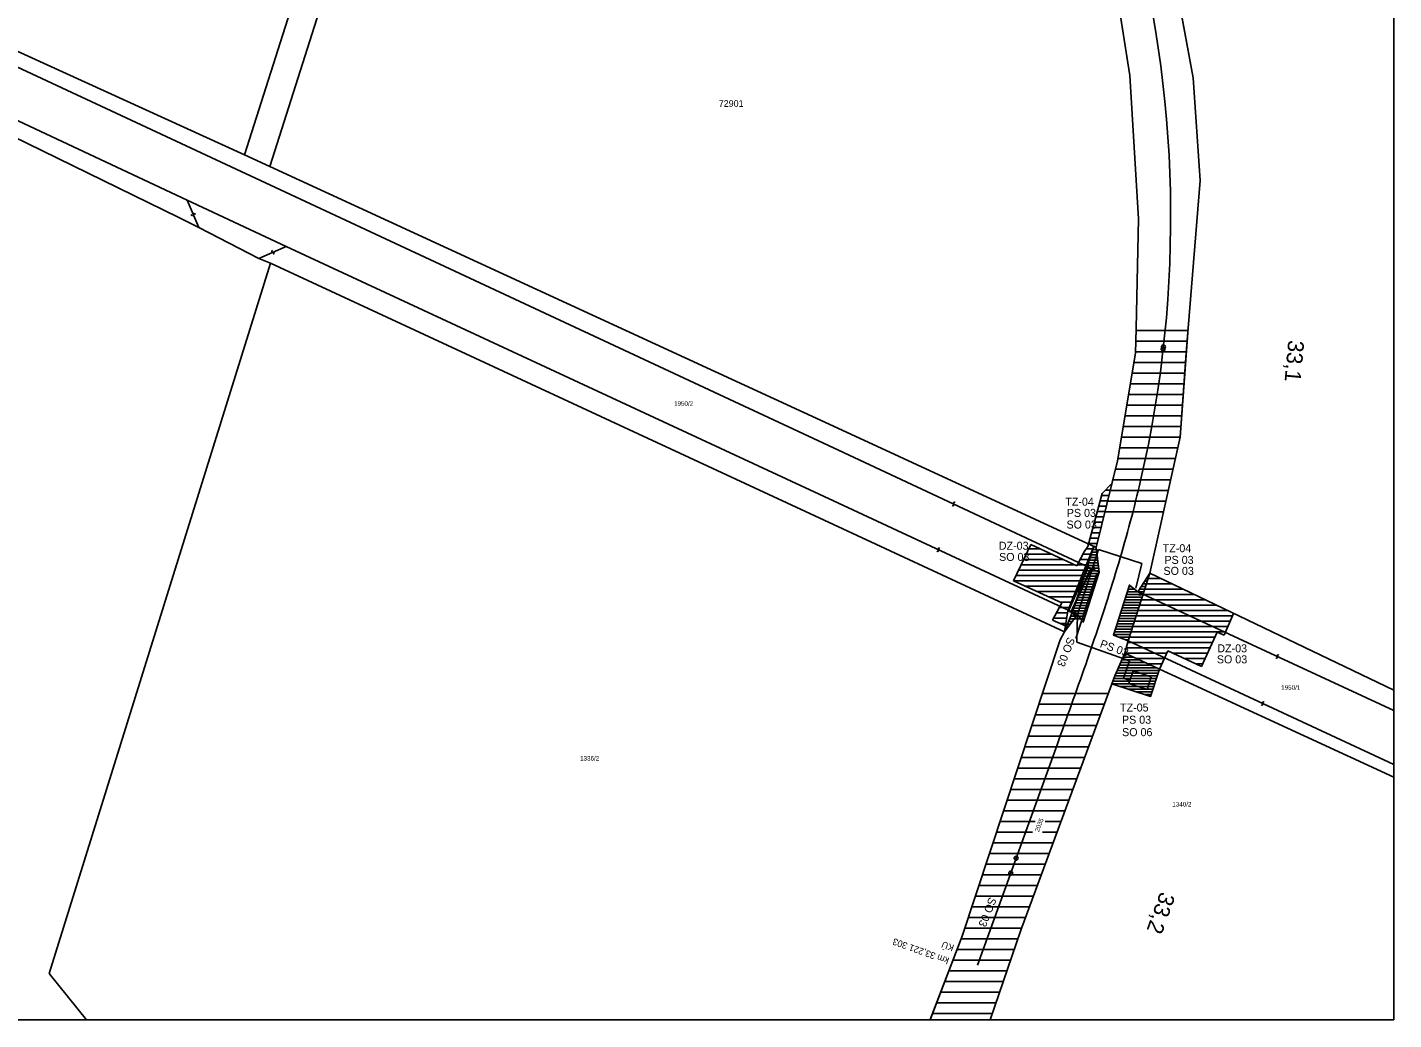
# Model space of a CAD drawing. Extents: x -792659 to -786947, y -1118170 to -1109641.
# Drawn here: x -787458.6 to -787202.6, y -1117485.6 to -1117299.6 of the extents above; entities that cross this region are included whole.
import ezdxf

# ---------------------------------------------------------------- set-up
doc = ezdxf.new("R2010")
doc.units = 0
doc.layers.add('1', color=7, linetype='Continuous')

msp = doc.modelspace()

# ---------------------------------------------------------------- linework, layer by layer
at = {"layer": '1'}
for p, q in [((-787360.49, -1117143.13), (-787417.96, -1117323.48)), ((-787413.22, -1117325.67), (-787356.33, -1117146.67)), ((-787252.03, -1117308.63), (-787255.71, -1117285.12)), ((-787244.19, -1117287.3), (-787240.18, -1117309.09)), ((-787417.96, -1117323.48), (-787462.74, -1117303.06)), ((-787307.59, -1117378.44), (-787464.41, -1117305.26)), ((-787250.41, -1117335.48), (-787252.03, -1117308.63)), ((-787240.18, -1117309.09), (-787238.86, -1117328.3)), ((-787428.71, -1117331.97), (-787468.36, -1117313.39)), ((-787430.26, -1117335.21), (-787469.59, -1117315.99)), ((-787413.22, -1117325.67), (-787417.96, -1117323.48)), ((-787413.22, -1117325.67), (-787307.59, -1117374.37)), ((-787238.86, -1117328.3), (-787241.11, -1117356)), ((-787410.13, -1117340.66), (-787428.71, -1117331.97)), ((-787428.71, -1117331.97), (-787426.53, -1117337.12)), ((-787426.53, -1117337.12), (-787430.26, -1117335.21)), ((-787250.86, -1117356.02), (-787250.41, -1117335.48)), ((-787415.24, -1117342.91), (-787426.53, -1117337.12)), ((-787410.13, -1117340.66), (-787415.24, -1117342.91)), ((-787307.59, -1117388.37), (-787410.13, -1117340.66)), ((-787413.04, -1117343.78), (-787454.54, -1117476.95)), ((-787413.04, -1117343.78), (-787415.24, -1117342.91)), ((-787307.59, -1117392.77), (-787413.04, -1117343.78)), ((-787250.96, -1117360.68), (-787250.86, -1117356.02)), ((-787250.87, -1117356.43), (-787241.14, -1117356.43)), ((-787241.11, -1117356), (-787242.61, -1117376.43)), ((-787250.91, -1117358.43), (-787241.3, -1117358.43)), ((-787254.36, -1117380.85), (-787250.96, -1117360.68)), ((-787251.26, -1117362.43), (-787241.61, -1117362.43)), ((-787250.96, -1117360.43), (-787241.54, -1117360.43)), ((-787251.59, -1117364.43), (-787241.75, -1117364.43)), ((-787251.93, -1117366.43), (-787241.9, -1117366.43)), ((-787252.27, -1117368.43), (-787242.04, -1117368.43)), ((-787252.94, -1117372.43), (-787242.32, -1117372.43)), ((-787252.6, -1117370.43), (-787242.18, -1117370.43)), ((-787258.37, -1117397.06), (-787307.59, -1117374.37)), ((-787253.28, -1117374.43), (-787242.47, -1117374.43)), ((-787253.61, -1117376.43), (-787242.61, -1117376.43)), ((-787242.61, -1117376.43), (-787248.32, -1117401.92)), ((-787307.59, -1117378.44), (-787257.76, -1117401.7)), ((-787307.59, -1117378.44), (-787257.76, -1117401.7)), ((-787253.95, -1117378.43), (-787243.06, -1117378.43)), ((-787258.37, -1117397.06), (-787254.36, -1117380.85)), ((-787254.75, -1117382.43), (-787243.95, -1117382.43)), ((-787254.29, -1117380.43), (-787243.51, -1117380.43)), ((-787255.42, -1117385.12), (-787257.23, -1117386.98)), ((-787255.63, -1117385.34), (-787255.47, -1117385.34)), ((-787255.25, -1117384.43), (-787244.4, -1117384.43)), ((-787257.23, -1117386.98), (-787259.93, -1117396.93)), ((-787257.33, -1117387.34), (-787255.96, -1117387.34)), ((-787256.6, -1117386.34), (-787255.72, -1117386.34)), ((-787255.74, -1117386.43), (-787244.85, -1117386.43)), ((-787261.83, -1117409.67), (-787307.59, -1117388.37)), ((-787307.59, -1117388.37), (-787261.83, -1117409.67)), ((-787258.14, -1117390.34), (-787256.71, -1117390.34)), ((-787257.87, -1117389.34), (-787256.46, -1117389.34)), ((-787257.6, -1117388.34), (-787256.21, -1117388.34)), ((-787256.73, -1117390.43), (-787245.75, -1117390.43)), ((-787256.23, -1117388.43), (-787245.3, -1117388.43)), ((-787264.26, -1117412.91), (-787307.59, -1117392.77)), ((-787258.68, -1117392.34), (-787257.2, -1117392.34)), ((-787258.41, -1117391.34), (-787256.95, -1117391.34)), ((-787259.5, -1117395.34), (-787257.94, -1117395.34)), ((-787259.23, -1117394.34), (-787257.7, -1117394.34)), ((-787258.95, -1117393.34), (-787257.45, -1117393.34)), ((-787270.59, -1117396.5), (-787273.84, -1117403.34)), ((-787270.98, -1117397.34), (-787268.79, -1117397.34)), ((-787270.59, -1117396.5), (-787261.95, -1117400.53)), ((-787262.5, -1117408.49), (-787258.77, -1117396.87)), ((-787260.58, -1117397.91), (-787261.95, -1117400.53)), ((-787261.83, -1117409.67), (-787257.92, -1117397.49)), ((-787261.83, -1117409.67), (-787257.92, -1117397.49)), ((-787259.93, -1117396.93), (-787260.58, -1117397.91)), ((-787260.2, -1117397.34), (-787258.96, -1117397.34)), ((-787259.77, -1117396.34), (-787258.19, -1117396.34)), ((-787259.13, -1117397.98), (-787258.25, -1117397.98)), ((-787258.97, -1117397.48), (-787258.31, -1117397.48)), ((-787258.77, -1117396.87), (-787258.77, -1117396.87)), ((-787258.37, -1117397.06), (-787258.77, -1117396.87)), ((-787257.76, -1117401.7), (-787258.37, -1117397.06)), ((-787257.92, -1117397.49), (-787249.76, -1117400.11)), ((-787257.92, -1117397.49), (-787249.76, -1117400.11)), ((-787272.41, -1117400.34), (-787262.36, -1117400.34)), ((-787271.93, -1117399.34), (-787264.5, -1117399.34)), ((-787271.46, -1117398.34), (-787266.65, -1117398.34)), ((-787263.65, -1117408.95), (-787259.91, -1117400.76)), ((-787259.82, -1117400.8), (-787263.56, -1117408.99)), ((-787261.85, -1117400.34), (-787260.17, -1117400.34)), ((-787261.33, -1117399.34), (-787259.77, -1117399.34)), ((-787260.8, -1117398.34), (-787259.36, -1117398.34)), ((-787259.93, -1117400.48), (-787257.92, -1117400.48)), ((-787259.91, -1117400.76), (-787259.27, -1117401.05)), ((-787259.91, -1117400.76), (-787259.27, -1117401.05)), ((-787259.77, -1117399.98), (-787257.99, -1117399.98)), ((-787259.61, -1117399.48), (-787258.05, -1117399.48)), ((-787259.45, -1117398.98), (-787258.12, -1117398.98)), ((-787259.29, -1117398.48), (-787258.18, -1117398.48)), ((-787249.76, -1117400.11), (-787250.89, -1117404.74)), ((-787249.76, -1117400.11), (-787250.89, -1117404.74)), ((-787273.84, -1117403.34), (-787264.78, -1117407.46)), ((-787273.84, -1117403.34), (-787261.38, -1117403.34)), ((-787273.36, -1117402.34), (-787260.98, -1117402.34)), ((-787272.89, -1117401.34), (-787260.58, -1117401.34)), ((-787263.1, -1117409.2), (-787259.37, -1117401.01)), ((-787259.27, -1117401.05), (-787263.01, -1117409.24)), ((-787258.14, -1117401.86), (-787262.14, -1117414.14)), ((-787260.78, -1117411.06), (-787257.76, -1117401.7)), ((-787260.73, -1117402.98), (-787258.17, -1117402.98)), ((-787260.57, -1117402.48), (-787258.01, -1117402.48)), ((-787260.42, -1117402.02), (-787260.42, -1117401.24)), ((-787260.41, -1117401.98), (-787257.85, -1117401.98)), ((-787260.25, -1117401.48), (-787257.79, -1117401.48)), ((-787260.09, -1117400.98), (-787257.85, -1117400.98)), ((-787248.32, -1117401.92), (-787252.33, -1117414.61)), ((-787248.32, -1117401.92), (-787250.51, -1117405.41)), ((-787249.26, -1117403.42), (-787248.79, -1117403.42)), ((-787248.95, -1117402.92), (-787248.64, -1117402.92)), ((-787248.63, -1117402.42), (-787248.48, -1117402.42)), ((-787248.63, -1117402.92), (-787246.23, -1117402.92)), ((-787271.64, -1117404.34), (-787261.79, -1117404.34)), ((-787269.44, -1117405.34), (-787262.19, -1117405.34)), ((-787261.69, -1117405.98), (-787259.14, -1117405.98)), ((-787261.53, -1117405.48), (-787258.98, -1117405.48)), ((-787261.37, -1117404.98), (-787258.82, -1117404.98)), ((-787261.21, -1117404.48), (-787258.66, -1117404.48)), ((-787261.05, -1117403.98), (-787258.5, -1117403.98)), ((-787260.89, -1117403.48), (-787258.33, -1117403.48)), ((-787252.11, -1117404.13), (-787255.1, -1117413.5)), ((-787252.68, -1117405.92), (-787249.58, -1117405.92)), ((-787252.52, -1117405.42), (-787249.43, -1117405.42)), ((-787252.36, -1117404.92), (-787251.12, -1117404.92)), ((-787252.2, -1117404.42), (-787251.75, -1117404.42)), ((-787250.51, -1117405.41), (-787252.11, -1117404.13)), ((-787250.51, -1117405.41), (-787202.59, -1117427.64)), ((-787250.51, -1117405.41), (-787202.59, -1117427.64)), ((-787250.2, -1117404.92), (-787249.27, -1117404.92)), ((-787249.89, -1117404.42), (-787249.11, -1117404.42)), ((-787249.58, -1117403.92), (-787248.95, -1117403.92)), ((-787249.56, -1117405.92), (-787239.97, -1117405.92)), ((-787249.25, -1117404.92), (-787242.06, -1117404.92)), ((-787248.94, -1117403.92), (-787244.15, -1117403.92)), ((-787267.24, -1117406.34), (-787262.6, -1117406.34)), ((-787264.78, -1117407.46), (-787266.5, -1117410.74)), ((-787265.24, -1117408.34), (-787263.4, -1117408.34)), ((-787265.04, -1117407.34), (-787263, -1117407.34)), ((-787262.5, -1117408.49), (-787264.26, -1117412.91)), ((-787262.49, -1117408.48), (-787259.95, -1117408.48)), ((-787262.33, -1117407.98), (-787259.79, -1117407.98)), ((-787262.17, -1117407.48), (-787259.62, -1117407.48)), ((-787262.01, -1117406.98), (-787259.46, -1117406.98)), ((-787261.85, -1117406.48), (-787259.3, -1117406.48)), ((-787253.48, -1117408.42), (-787250.37, -1117408.42)), ((-787253.32, -1117407.92), (-787250.22, -1117407.92)), ((-787253.16, -1117407.42), (-787250.06, -1117407.42)), ((-787253, -1117406.92), (-787249.9, -1117406.92)), ((-787252.84, -1117406.42), (-787249.74, -1117406.42)), ((-787250.18, -1117407.92), (-787235.8, -1117407.92)), ((-787249.87, -1117406.92), (-787237.88, -1117406.92)), ((-787266.5, -1117410.74), (-787264.09, -1117411.76)), ((-787266.29, -1117410.34), (-787263.87, -1117410.34)), ((-787265.76, -1117409.34), (-787263.71, -1117409.34)), ((-787264.26, -1117412.91), (-787261.83, -1117409.67)), ((-787263.01, -1117409.24), (-787263.65, -1117408.95)), ((-787263.49, -1117410.98), (-787262.81, -1117410.98)), ((-787263.29, -1117410.48), (-787262.44, -1117410.48)), ((-787263.09, -1117409.98), (-787262.06, -1117409.98)), ((-787262.89, -1117409.48), (-787260.34, -1117409.48)), ((-787262.69, -1117408.98), (-787260.11, -1117408.98)), ((-787262.4, -1117410.43), (-787261.26, -1117410.43)), ((-787262, -1117414.84), (-787261.83, -1117409.67)), ((-787262, -1117414.84), (-787261.83, -1117409.67)), ((-787261.83, -1117409.67), (-787260.78, -1117411.06)), ((-787261.6, -1117409.98), (-787260.43, -1117409.98)), ((-787261.22, -1117410.48), (-787260.59, -1117410.48)), ((-787260.84, -1117410.98), (-787260.75, -1117410.98)), ((-787254.28, -1117410.92), (-787251.16, -1117410.92)), ((-787254.12, -1117410.42), (-787251.01, -1117410.42)), ((-787253.96, -1117409.92), (-787250.85, -1117409.92)), ((-787253.8, -1117409.42), (-787250.69, -1117409.42)), ((-787253.64, -1117408.92), (-787250.53, -1117408.92)), ((-787251.12, -1117410.92), (-787233.23, -1117410.92)), ((-787250.8, -1117409.92), (-787232.78, -1117409.92)), ((-787250.49, -1117408.92), (-787233.71, -1117408.92)), ((-787234.39, -1117413.52), (-787232.58, -1117409.46)), ((-787265.1, -1117414.39), (-787264.26, -1117412.91)), ((-787265.09, -1117411.34), (-787264.02, -1117411.34)), ((-787264.09, -1117412.48), (-787263.94, -1117412.48)), ((-787263.89, -1117411.98), (-787263.56, -1117411.98)), ((-787263.69, -1117411.48), (-787263.19, -1117411.48)), ((-787255.1, -1117413.5), (-787252.33, -1117414.61)), ((-787255.07, -1117413.42), (-787251.95, -1117413.42)), ((-787254.91, -1117412.92), (-787251.8, -1117412.92)), ((-787254.76, -1117412.42), (-787251.64, -1117412.42)), ((-787254.68, -1117412.21), (-787254.68, -1117412.18)), ((-787254.6, -1117411.92), (-787251.48, -1117411.92)), ((-787254.44, -1117411.42), (-787251.32, -1117411.42)), ((-787251.74, -1117412.92), (-787234.12, -1117412.92)), ((-787251.43, -1117411.92), (-787233.68, -1117411.92)), ((-787238.6, -1117419.4), (-787235.68, -1117412.93)), ((-787235.68, -1117412.93), (-787234.39, -1117413.52)), ((-787283.43, -1117469.91), (-787265.1, -1117414.39)), ((-787265.11, -1117414.43), (-787265.07, -1117414.43)), ((-787252.08, -1117418.35), (-787262, -1117414.84)), ((-787252.08, -1117418.35), (-787262, -1117414.84)), ((-787254.05, -1117413.92), (-787252.11, -1117413.92)), ((-787252.33, -1117414.61), (-787252.97, -1117416.89)), ((-787252.8, -1117414.42), (-787252.27, -1117414.42)), ((-787252.67, -1117415.92), (-787237.03, -1117415.92)), ((-787252.36, -1117414.92), (-787236.58, -1117414.92)), ((-787202.59, -1117437.77), (-787252.33, -1117414.61)), ((-787252.05, -1117413.92), (-787236.13, -1117413.92)), ((-787252.97, -1117416.89), (-787254.84, -1117421.14)), ((-787253.73, -1117418.62), (-787249.22, -1117418.62)), ((-787253.51, -1117418.12), (-787250.3, -1117418.12)), ((-787253.29, -1117417.62), (-787251.39, -1117417.62)), ((-787253.23, -1117421.61), (-787252.08, -1117418.35)), ((-787253.07, -1117417.12), (-787252.47, -1117417.12)), ((-787246.49, -1117419.88), (-787252.97, -1117416.89)), ((-787252.9, -1117416.92), (-787245.12, -1117416.92)), ((-787250.74, -1117417.92), (-787245.58, -1117417.92)), ((-787246.49, -1117419.88), (-787244.91, -1117416.46)), ((-787238.6, -1117419.4), (-787244.91, -1117416.46)), ((-787243.93, -1117416.92), (-787237.48, -1117416.92)), ((-787241.78, -1117417.92), (-787237.93, -1117417.92)), ((-787254.84, -1117421.14), (-787272.47, -1117468.81)), ((-787254.83, -1117421.12), (-787246.9, -1117421.12)), ((-787254.61, -1117420.62), (-787246.73, -1117420.62)), ((-787254.39, -1117420.12), (-787246.57, -1117420.12)), ((-787254.17, -1117419.62), (-787247.05, -1117419.62)), ((-787253.95, -1117419.12), (-787248.14, -1117419.12)), ((-787252.22, -1117422.6), (-787251.44, -1117420.23)), ((-787251.44, -1117420.23), (-787248.02, -1117421.35)), ((-787248.57, -1117418.92), (-787246.05, -1117418.92)), ((-787248.16, -1117424.99), (-787246.49, -1117419.88)), ((-787239.63, -1117418.92), (-787238.39, -1117418.92)), ((-787255.39, -1117422.62), (-787248.16, -1117424.99)), ((-787255.39, -1117422.62), (-787247.39, -1117422.62)), ((-787255.2, -1117422.12), (-787247.22, -1117422.12)), ((-787255.02, -1117421.62), (-787247.06, -1117421.62)), ((-787253.86, -1117423.12), (-787247.55, -1117423.12)), ((-787252.06, -1117422.04), (-787253.23, -1117421.61)), ((-787252.34, -1117423.62), (-787247.71, -1117423.62)), ((-787248.8, -1117423.73), (-787252.22, -1117422.6)), ((-787248.02, -1117421.35), (-787248.8, -1117423.73)), ((-787269.08, -1117426.43), (-787256.8, -1117426.43)), ((-787268.42, -1117424.43), (-787256.06, -1117424.43)), ((-787250.81, -1117424.12), (-787247.88, -1117424.12)), ((-787249.29, -1117424.62), (-787248.04, -1117424.62)), ((-787269.73, -1117428.43), (-787257.54, -1117428.43)), ((-787270.4, -1117430.43), (-787258.28, -1117430.43)), ((-787265.68, -1117434.06), (-787280.56, -1117475.36)), ((-787271.06, -1117432.43), (-787259.02, -1117432.43)), ((-787272.38, -1117436.43), (-787260.49, -1117436.43)), ((-787271.72, -1117434.43), (-787259.76, -1117434.43)), ((-787273.04, -1117438.43), (-787261.23, -1117438.43)), ((-787273.7, -1117440.43), (-787261.97, -1117440.43)), ((-787274.36, -1117442.43), (-787262.71, -1117442.43)), ((-787275.68, -1117446.43), (-787264.19, -1117446.43)), ((-787275.02, -1117444.43), (-787263.45, -1117444.43)), ((-787276.34, -1117448.43), (-787269.79, -1117448.43)), ((-787267.88, -1117448.43), (-787264.93, -1117448.43)), ((-787277, -1117450.43), (-787270.3, -1117450.43)), ((-787268.4, -1117450.43), (-787265.67, -1117450.43)), ((-787278.32, -1117454.43), (-787267.15, -1117454.43)), ((-787277.66, -1117452.43), (-787266.41, -1117452.43)), ((-787278.98, -1117456.43), (-787267.89, -1117456.43)), ((-787279.64, -1117458.43), (-787268.63, -1117458.43)), ((-787280.3, -1117460.43), (-787269.37, -1117460.43)), ((-787281.62, -1117464.43), (-787270.85, -1117464.43)), ((-787280.96, -1117462.43), (-787270.11, -1117462.43)), ((-787282.28, -1117466.43), (-787271.59, -1117466.43)), ((-787289.47, -1117485.59), (-787283.43, -1117469.91)), ((-787282.94, -1117468.43), (-787272.33, -1117468.43)), ((-787272.47, -1117468.81), (-787278.2, -1117485.59)), ((-787284.4, -1117472.43), (-787273.71, -1117472.43)), ((-787283.63, -1117470.43), (-787273.02, -1117470.43)), ((-787285.17, -1117474.43), (-787274.39, -1117474.43)), ((-787454.54, -1117476.95), (-787447.56, -1117485.59)), ((-787285.94, -1117476.43), (-787275.07, -1117476.43)), ((-787286.71, -1117478.43), (-787275.76, -1117478.43)), ((-787288.25, -1117482.43), (-787277.12, -1117482.43)), ((-787287.48, -1117480.43), (-787276.44, -1117480.43)), ((-787289.02, -1117484.43), (-787277.8, -1117484.43))]:
    msp.add_line(p, q, dxfattribs=at)
for points in [[(-787627.26, -1116934.58), (-787202.59, -1116934.58), (-787202.59, -1117485.59), (-787627.26, -1117485.59)], [(-787264.26, -1117412.91), (-787263.65, -1117408.95), (-787258.77, -1117396.87), (-787258.37, -1117397.06), (-787257.76, -1117401.7), (-787260.78, -1117411.06), (-787261.83, -1117409.67)], [(-787248.32, -1117401.92), (-787252.33, -1117414.61), (-787255.1, -1117413.5), (-787252.11, -1117404.13), (-787250.51, -1117405.41)], [(-787252.97, -1117416.89), (-787246.49, -1117419.88), (-787248.16, -1117424.99), (-787255.39, -1117422.62), (-787254.84, -1117421.14)]]:
    msp.add_lwpolyline(points, close=True, dxfattribs=at)
for points in [[(-787244.19, -1117287.3), (-787240.18, -1117309.09), (-787238.86, -1117328.3), (-787241.11, -1117356), (-787242.61, -1117376.43), (-787248.32, -1117401.92), (-787250.51, -1117405.41), (-787252.11, -1117404.13), (-787255.1, -1117413.5), (-787252.33, -1117414.61), (-787252.97, -1117416.89), (-787254.84, -1117421.14), (-787272.47, -1117468.81), (-787278.2, -1117485.59), (-787289.47, -1117485.57), (-787283.43, -1117469.91), (-787265.1, -1117414.39), (-787264.26, -1117412.91), (-787261.83, -1117409.67), (-787260.78, -1117411.06), (-787257.76, -1117401.7), (-787258.37, -1117397.06), (-787254.36, -1117380.85), (-787250.96, -1117360.68), (-787250.86, -1117356.02), (-787250.41, -1117335.48), (-787252.03, -1117308.63), (-787255.71, -1117285.12)], [(-787202.59, -1117337.09), (-787202.59, -1117485.59)], [(-787289.47, -1117485.59), (-787283.43, -1117469.91), (-787265.1, -1117414.39), (-787264.26, -1117412.91), (-787261.83, -1117409.67), (-787260.78, -1117411.06), (-787257.76, -1117401.7), (-787258.37, -1117397.06), (-787254.36, -1117380.85), (-787250.96, -1117360.68), (-787250.86, -1117356.02)], [(-787241.11, -1117356), (-787242.61, -1117376.43), (-787248.32, -1117401.92), (-787250.51, -1117405.41), (-787252.11, -1117404.13), (-787255.1, -1117413.5), (-787252.33, -1117414.61), (-787252.97, -1117416.89), (-787254.84, -1117421.14), (-787272.47, -1117468.81), (-787278.2, -1117485.59)], [(-787250.86, -1117356.02), (-787250.96, -1117360.68), (-787254.36, -1117380.85), (-787258.37, -1117397.06)], [(-787248.32, -1117401.92), (-787242.61, -1117376.43), (-787241.48, -1117360.62), (-787241.11, -1117356)], [(-787265.68, -1117434.06), (-787265.34, -1117433.12), (-787265, -1117432.18), (-787264.66, -1117431.24), (-787264.32, -1117430.3), (-787263.99, -1117429.35), (-787263.65, -1117428.41), (-787263.31, -1117427.47), (-787262.98, -1117426.53), (-787262.64, -1117425.59), (-787262.3, -1117424.65), (-787261.97, -1117423.7), (-787261.64, -1117422.76), (-787261.3, -1117421.82), (-787260.97, -1117420.87), (-787260.64, -1117419.93), (-787260.31, -1117418.99), (-787259.99, -1117418.04), (-787259.66, -1117417.1), (-787259.33, -1117416.15), (-787259.01, -1117415.2), (-787258.69, -1117414.26), (-787258.37, -1117413.31), (-787258.05, -1117412.36), (-787257.74, -1117411.41), (-787257.42, -1117410.46), (-787257.11, -1117409.51), (-787256.8, -1117408.56), (-787256.49, -1117407.61), (-787256.19, -1117406.66), (-787255.89, -1117405.7), (-787255.58, -1117404.75), (-787255.29, -1117403.8), (-787254.99, -1117402.84), (-787254.7, -1117401.88), (-787254.41, -1117400.93), (-787254.12, -1117399.97), (-787253.84, -1117399.01), (-787253.56, -1117398.05), (-787253.28, -1117397.09), (-787253.01, -1117396.13), (-787252.74, -1117395.16), (-787252.47, -1117394.2), (-787252.21, -1117393.24), (-787251.95, -1117392.27), (-787251.69, -1117391.3), (-787251.44, -1117390.34), (-787251.19, -1117389.37), (-787250.95, -1117388.4), (-787250.71, -1117387.43), (-787250.47, -1117386.46), (-787250.24, -1117385.48), (-787250.01, -1117384.51)], [(-787264.26, -1117412.91), (-787261.83, -1117409.67), (-787260.78, -1117411.06), (-787257.76, -1117401.7), (-787258.37, -1117397.06)], [(-787248.32, -1117401.92), (-787250.51, -1117405.41), (-787252.11, -1117404.13), (-787255.1, -1117413.5), (-787252.33, -1117414.61), (-787252.97, -1117416.89)], [(-787202.59, -1117423.83), (-787248.32, -1117401.92)], [(-787289.47, -1117485.59), (-787283.43, -1117469.91), (-787265.1, -1117414.39), (-787264.26, -1117412.91)], [(-787252.97, -1117416.89), (-787254.84, -1117421.14), (-787272.47, -1117468.81), (-787278.2, -1117485.59)], [(-787202.59, -1117440.15), (-787252.97, -1117416.89)], [(-787202.59, -1117485.59), (-787307.59, -1117485.59)]]:
    msp.add_lwpolyline(points, dxfattribs=at)
for centre in [(-787245.8, -1117359.91), (-787245.74, -1117359.48), (-787273.34, -1117455.32), (-787274.35, -1117458.12)]:
    msp.add_circle(centre, 0.375, dxfattribs=at)
for centre, radius, start, end in [((-787463.39, -1117335.21), 219, 346.9911, 43.7408), ((-787427.72, -1117334.68), 0.187, 178.4834, 358.4834), ((-787427.35, -1117334.69), 0.188, 358.4834, 178.4834), ((-787412.65, -1117341.57), 0.188, 100.8329, 280.8328), ((-787412.58, -1117341.94), 0.187, 280.8329, 100.8329), ((-787285.2, -1117389.07), 0.188, 221.966, 41.966), ((-787284.92, -1117388.81), 0.188, 41.966, 221.9659), ((-787288.06, -1117397.64), 0.188, 221.966, 41.966), ((-787287.78, -1117397.38), 0.188, 41.966, 221.9659), ((-787258.77, -1117400.98), 0.188, 41.966, 221.9659), ((-787258.77, -1117400.99), 0.188, 41.966, 221.9659), ((-787259.05, -1117401.23), 0.188, 221.966, 41.966), ((-787259.05, -1117401.25), 0.188, 221.966, 41.966), ((-787250.15, -1117405.82), 0.188, 221.966, 41.966), ((-787249.87, -1117405.57), 0.188, 41.966, 221.9659), ((-787262.49, -1117409.55), 0.188, 221.966, 41.966), ((-787262.43, -1117409.58), 0.188, 221.966, 41.966), ((-787262.21, -1117409.3), 0.188, 41.966, 221.9659), ((-787262.15, -1117409.32), 0.188, 41.966, 221.9659), ((-787224.55, -1117417.65), 0.188, 221.966, 41.966), ((-787224.27, -1117417.39), 0.188, 41.966, 221.9659), ((-787227.28, -1117426.45), 0.188, 221.966, 41.966), ((-787227, -1117426.19), 0.188, 41.966, 221.9659)]:
    msp.add_arc(centre, radius, start, end, dxfattribs=at)

# ---------------------------------------------------------------- texts
for s, height, p in [('72901', 1.25, (-787329.07, -1117314.5)), ('1950/2', 0.85, (-787337.45, -1117370.53)), ('TZ-04', 1.5, (-787264.13, -1117389.25)), ('PS 03', 1.5, (-787263.85, -1117391.35)), ('SO 03', 1.5, (-787263.9, -1117393.54)), ('SO 03', 1.5, (-787276.54, -1117399.61)), ('DZ-03', 1.5, (-787276.59, -1117397.51)), ('TZ-04', 1.5, (-787245.88, -1117397.97)), ('SO 03', 1.5, (-787245.73, -1117402.22)), ('PS 03', 1.5, (-787245.55, -1117400.16)), ('DZ-03', 1.5, (-787235.64, -1117416.74)), ('SO 03', 1.5, (-787235.73, -1117418.8)), ('1950/1', 0.85, (-787223.67, -1117423.76)), ('TZ-05', 1.5, (-787253.87, -1117427.83)), ('PS 03', 1.5, (-787253.51, -1117430.12)), ('SO 06', 1.5, (-787253.49, -1117432.45)), ('1336/2', 0.85, (-787355.06, -1117437.03)), ('1340/2', 0.85, (-787244.08, -1117445.64))]:
    msp.add_text(s, height=height, dxfattribs=at).set_placement(p)
for s, height, rotation, p in [('33,1', 3, 264.8984, (-787222.34, -1117358.14)), ('SO 03', 1.5, 248.6161, (-787263.66, -1117413.76)), ('PS 03', 1.5, 340.0492, (-787257.76, -1117415.73)), ('2035', 0.85, 69.9338, (-787269.07, -1117450.47)), ('33,2', 3, 250.1954, (-787246.29, -1117461.46)), ('SO 03', 1.5, 248.6161, (-787278.37, -1117462.52)), ('km 33,221 303', 1.25, 160.1889, (-787285.8, -1117474.04)), ('KÚ', 1.25, 160.1888, (-787284.86, -1117471.64))]:
    msp.add_text(s, height=height, rotation=rotation, dxfattribs=at).set_placement(p)

doc.saveas('drawing.dxf')
